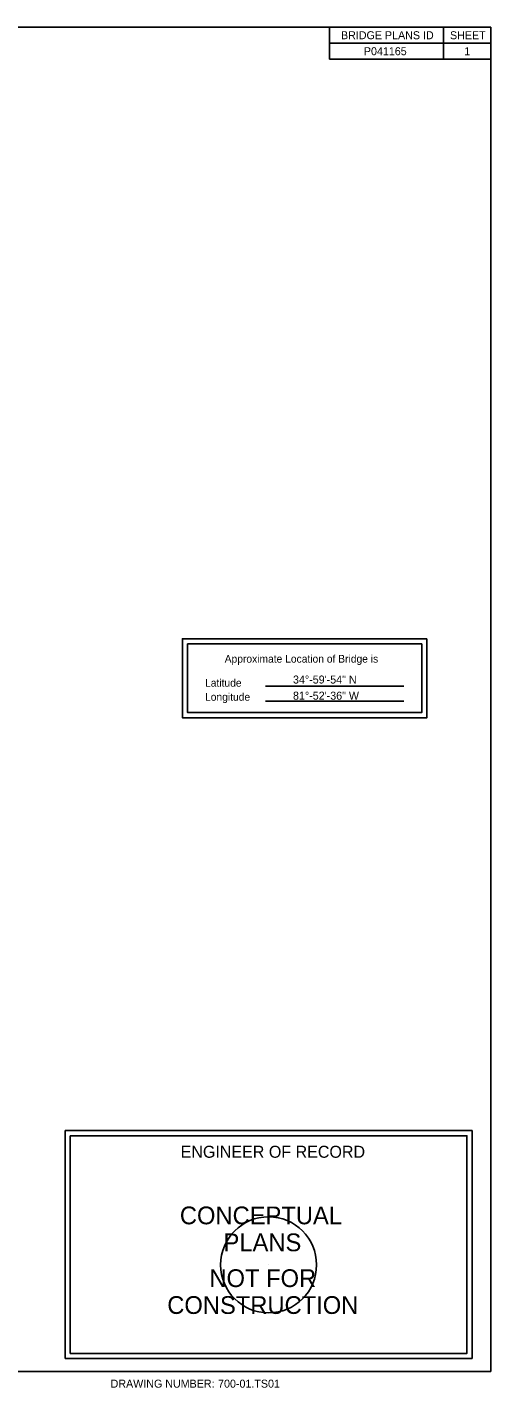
# Model space of a CAD drawing. Extents: x 0 to 4.05, y 0.02 to 4.32.
# Drawn here: x 2.188 to 2.792, y 0.02 to 1.792 of the extents above; entities that cross this region are included whole.
import ezdxf

# ---------------------------------------------------------------- set-up
doc = ezdxf.new("R2010")
doc.units = 0
for name, color, linetype in [('BR_AUTO DIMENSION', 7, 'Continuous'), ('BR_BORDER LINES', 7, 'Continuous'), ('BR_DETAILS', 7, 'Continuous'), ('Default', 7, 'Continuous'), ('NoPlot', 7, 'Continuous')]:
    doc.layers.add(name, color=color, linetype=linetype)

msp = doc.modelspace()

# ---------------------------------------------------------------- linework, layer by layer
at = {"layer": 'BR_BORDER LINES'}
for p, q in [((2.5815, 1.7917), (2.5815, 1.75)), ((2.73, 1.7917), (2.73, 1.75)), ((2.7917, 1.7708), (2.5815, 1.7708)), ((2.7917, 1.75), (2.5815, 1.75))]:
    msp.add_line(p, q, dxfattribs=at)
msp.add_lwpolyline([(0.1667, 1.7917), (2.7917, 1.7917), (2.7917, 0.0417), (0.1667, 0.0417)], close=True, dxfattribs=at)
at = {"layer": 'BR_DETAILS'}
for p, q in [((2.4982, 0.9337), (2.6784, 0.9337)), ((2.4982, 0.9144), (2.6784, 0.9144))]:
    msp.add_line(p, q, dxfattribs=at)
for points in [[(2.7084, 0.9954), (2.39, 0.9954), (2.39, 0.8927), (2.7084, 0.8927)], [(2.7017, 0.9887), (2.3966, 0.9887), (2.3966, 0.8994), (2.7017, 0.8994)], [(2.2372, 0.3551), (2.7672, 0.3551), (2.7672, 0.0585), (2.2372, 0.0585)], [(2.2439, 0.3485), (2.7606, 0.3485), (2.7606, 0.0651), (2.2439, 0.0651)]]:
    msp.add_lwpolyline(points, close=True, dxfattribs=at)
at = {"layer": 'NoPlot'}
msp.add_line((2.5022, 0.1804), (2.5022, 0.1804), dxfattribs=at)
msp.add_circle((2.5022, 0.1804), 0.0625, dxfattribs=at)

# ---------------------------------------------------------------- texts
at = {"layer": 'BR_AUTO DIMENSION'}
for s, p in [('34°-59\'-54" N', (2.534, 0.9372)), ('81°-52\'-36" W', (2.534, 0.9162))]:
    msp.add_text(s, height=0.010417, dxfattribs=at).set_placement(p)
at = {"layer": 'BR_DETAILS'}
for s, p in [('Approximate Location of Bridge is', (2.445, 0.9644)), ('Latitude', (2.4194, 0.9331)), ('Longitude', (2.4194, 0.9148))]:
    msp.add_text(s, height=0.01, dxfattribs=at).set_placement(p)
for s, height, p in [('CONCEPTUAL', 0.02311, (2.3866, 0.2332)), ('PLANS', 0.02311, (2.4435, 0.1981)), ('NOT FOR', 0.02311, (2.4251, 0.1515)), ('CONSTRUCTION', 0.023108, (2.3702, 0.1165))]:
    msp.add_text(s, height=height, rotation=360, dxfattribs=at).set_placement(p)
at = {"layer": 'Default'}
for s, height, p in [('BRIDGE PLANS ID', 0.010417, (2.5965, 1.776)), ('SHEET', 0.01042, (2.7385, 1.776)), ('P041165', 0.01042, (2.6263, 1.7552)), ('1', 0.0104, (2.7572, 1.7552)), ('ENGINEER OF RECORD', 0.015625, (2.3876, 0.3198)), ('DRAWING NUMBER:', 0.010417, (2.2964, 0.0205)), ('700-01.TS01', 0.010417, (2.4364, 0.0205))]:
    msp.add_text(s, height=height, dxfattribs=at).set_placement(p)

doc.saveas('drawing.dxf')
